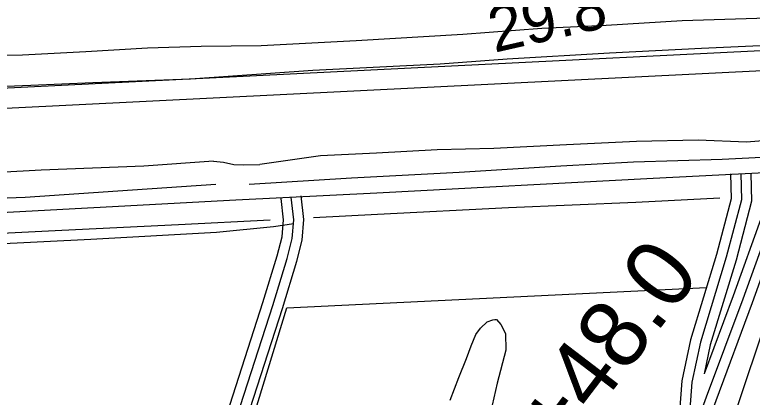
# Model space of a CAD drawing. Extents: x 3297772 to 3335630, y 634068 to 659439.
# Drawn here: x 3330240 to 3331326, y 644667 to 645230 of the extents above; entities that cross this region are included whole.
import ezdxf

# ---------------------------------------------------------------- set-up
doc = ezdxf.new("R2010")
doc.units = 0
for name, color, linetype in [('V-DTCH-CNTR', 7, 'Continuous'), ('V-FLOD-BASE', 7, 'Continuous'), ('V-LEVE-TOET', 7, 'Continuous'), ('V-RIVR-RANG', 7, 'Continuous'), ('V-ROAD-CNTR', 7, 'Continuous'), ('V-SITE-VEGE', 7, 'Continuous'), ('V-SURV-IDEN', 7, 'Continuous'), ('V-SURV-LINE', 7, 'Continuous'), ('V-TOPO-SHOR', 7, 'Continuous'), ('V-UTIL-LINE', 7, 'Continuous')]:
    doc.layers.add(name, color=color, linetype=linetype)

msp = doc.modelspace()

# ---------------------------------------------------------------- linework, layer by layer
at = {"layer": 'V-DTCH-CNTR'}
for points in [[(3330650.4, 644922.4), (3330620.8, 644918.1), (3330536.8, 644909.3), (3330351.7, 644899), (3330202.7, 644891.8), (3330031.6, 644885), (3329912.9, 644877), (3329903.6, 644873.9), (3329893.9, 644865.3), (3329882.2, 644838.1), (3329870.4, 644792.2), (3329872, 644779.8), (3329883.6, 644767.7), (3329927.2, 644745.5), (3329995.6, 644720.9), (3330134.4, 644676.8), (3330282.9, 644628.4), (3330438.4, 644573.4), (3330452.8, 644562.5), (3330477.3, 644539.9), (3330530.5, 644517.2)], [(3331338.7, 644758.7), (3331279.3, 644581.4), (3331213.4, 644360.6), (3331154.8, 644170), (3331138, 644102.8), (3331140.3, 644093.4), (3331157.4, 644076.3), (3331163.2, 644065), (3331154.6, 644025.8), (3331099.2, 643854.3)]]:
    msp.add_lwpolyline(points, dxfattribs=at)
at = {"layer": 'V-FLOD-BASE'}
msp.add_lwpolyline([(3329075.4, 645065.6), (3329181.4, 645069.7), (3329301, 645075.7), (3329468.5, 645084.8), (3329631.1, 645097.4), (3329730.9, 645103.5), (3329836.9, 645110.3), (3329923.2, 645113.3), (3329989.4, 645114), (3330118.2, 645120.5), (3330263.3, 645126.1), (3330354.7, 645130.2), (3330498.2, 645135.5), (3330678.5, 645148.4), (3330866.2, 645157.5), (3330964.5, 645165.1), (3331115.4, 645173.9), (3331250.8, 645180.7), (3331391.3, 645187.1), (3331544.1, 645193.1), (3331585.9, 645197.7), (3331629.3, 645203.4), (3331672.6, 645213.8)], dxfattribs=at)
at = {"layer": 'V-LEVE-TOET'}
for points in [[(3329320.5, 645126.1), (3329430.8, 645131.5), (3329551.3, 645142.3), (3329662.3, 645148.4), (3329784.7, 645155.7), (3329921.2, 645163), (3330045.2, 645164.4), (3330144.9, 645170.5), (3330251.2, 645170.8), (3330344.3, 645175.8), (3330435, 645181.1), (3330514, 645183.4), (3330602.4, 645184.8), (3330742.4, 645192.1), (3330899.6, 645201.3), (3331015.7, 645210.2), (3331110.7, 645214.4), (3331222.6, 645221.3), (3331348.1, 645225.4)], [(3331383.3, 645048), (3331317.2, 645042.2), (3331246.1, 645045.4), (3331155.3, 645043.5), (3331052.1, 645038.6), (3330945, 645033.2), (3330861.7, 645031), (3330772.5, 645026), (3330689.6, 645022.2), (3330600.4, 645009.8)], [(3330532.4, 645014.5), (3330429.6, 645007.2), (3330278.6, 645001.1), (3330153.1, 644994.6), (3330013.5, 644989.3), (3329885.2, 644981.7), (3329760.5, 644971.6), (3329635, 644964.7), (3329489.1, 644959), (3329362, 644946.3), (3329245.5, 644938.2), (3329112.9, 644932.1), (3328981.1, 644925.6), (3328912.7, 644919.8), (3328837.6, 644910.5), (3328670.2, 644897.4)], [(3330532.4, 645014.5), (3330546.8, 645012.9), (3330562.2, 645009.6), (3330575.8, 645009.1), (3330600.4, 645009.8)]]:
    msp.add_lwpolyline(points, dxfattribs=at)
at = {"layer": 'V-ROAD-CNTR'}
for points in [[(3325736.1, 644715.3), (3326147.1, 644722), (3326579.4, 644746.2), (3326860.4, 644766.7), (3327040, 644782.7), (3327405, 644790.9), (3327728.6, 644805), (3328365, 644841.2), (3328961, 644870), (3329423.1, 644898), (3329955.7, 644924.8), (3330565.3, 644957.4), (3330772.6, 644967.9), (3331179.9, 644989.5), (3331441, 645002.9)], [(3331363.5, 645004.4), (3331340, 644934.8), (3331297.5, 644816.5), (3331254.7, 644701.9)], [(3331377.7, 644999.7), (3331354.2, 644929.8), (3331311.5, 644811.3), (3331257.8, 644667.3), (3331227.6, 644585.4), (3331200.8, 644505.1), (3331116.1, 644248.6), (3330933.1, 643667.9), (3330742.9, 643076.2), (3330534.9, 642422.4)], [(3331391.9, 644994.9), (3331368.3, 644924.9), (3331325.6, 644806.2), (3331271.9, 644662), (3331241.7, 644580.4), (3331215.1, 644500.4), (3331130.3, 644244), (3330947.4, 643663.4), (3330757.2, 643071.6), (3330549.2, 642417.8)], [(3331293.7, 644995.8), (3331294.4, 644959.3), (3331273, 644877.2), (3331234.6, 644751.9), (3331221.9, 644691.5), (3331214.6, 644593.9)], [(3331308.7, 644996.1), (3331309.5, 644957.6), (3331287.4, 644873.1), (3331249.2, 644748.2), (3331236.7, 644689.4), (3331229.4, 644590.2)], [(3331323.7, 644996.4), (3331324.5, 644955.8), (3331301.8, 644869), (3331263.7, 644744.4), (3331254.7, 644701.9)], [(3330284.2, 643841.6), (3330326.4, 643963.9), (3330442.8, 644304.7), (3330552.3, 644643.1), (3330605.1, 644806.5), (3330626, 644875.4), (3330633.2, 644903.3), (3330635.4, 644928.2), (3330631.7, 644959.7)], [(3330288.8, 643808.9), (3330340.5, 643959), (3330457, 644300), (3330566.6, 644638.5), (3330619.4, 644802), (3330640.5, 644871.4), (3330648, 644900.8), (3330650.5, 644928.4), (3330646.6, 644961.5)], [(3330298.5, 643792.1), (3330354.7, 643954.1), (3330471.3, 644295.2), (3330580.9, 644633.9), (3330633.7, 644797.6), (3330654.9, 644867.4), (3330662.8, 644898.2), (3330665.5, 644928.6), (3330661.5, 644963.3)]]:
    msp.add_lwpolyline(points, dxfattribs=at)
at = {"layer": 'V-SITE-VEGE'}
msp.add_lwpolyline([(3330880.9, 644662.9), (3330893.7, 644696.3), (3330905, 644724.3), (3330911.7, 644743), (3330918.7, 644759.7), (3330925.3, 644769), (3330935, 644778), (3330943.6, 644781.1), (3330946.7, 644781.5), (3330949.1, 644781.5), (3330955.3, 644774.4), (3330962.3, 644761.2), (3330962.6, 644736.7), (3330950.1, 644687.7), (3330935.3, 644623.2)], dxfattribs=at)
at = {"layer": 'V-SURV-LINE'}
for points in [[(3329001, 645061.3), (3331556, 645188.1)], [(3331557.5, 645158.2), (3329002.4, 645031.3)]]:
    msp.add_lwpolyline(points, dxfattribs=at)
at = {"layer": 'V-TOPO-SHOR'}
for points in [[(3331369.1, 645021.4), (3331281.2, 645016.8), (3331150.9, 645013.1), (3331043.5, 645007.3), (3330894.2, 644997.8)], [(3330894.2, 644997.8), (3330735.5, 644989.4), (3330585, 644979.9)], [(3330535.6, 644980.3), (3330413, 644971.9), (3330254.7, 644961.2), (3330054.8, 644953.7), (3329889.4, 644941.8)], [(3331277.6, 644960), (3331153.9, 644953.9), (3330966.4, 644945.6), (3330773.9, 644936.1), (3330679.4, 644931.2)], [(3330615.6, 644927.7), (3330480.7, 644920.9), (3330308.7, 644912.5), (3330161, 644904.9), (3329987.1, 644895.4), (3329888.8, 644886.8)]]:
    msp.add_lwpolyline(points, dxfattribs=at)
at = {"layer": 'V-UTIL-LINE'}
for points in [[(3330640.2, 644798.6), (3331258.2, 644828.5)], [(3330502.7, 644350.2), (3330640.2, 644798.6)]]:
    msp.add_lwpolyline(points, dxfattribs=at)

# ---------------------------------------------------------------- texts
at = {"layer": 'V-RIVR-RANG'}
msp.add_text('29.8', height=67, rotation=12.7883, dxfattribs=at).set_placement((3330945.8, 645173.8))
at = {"layer": 'V-SURV-IDEN'}
msp.add_text('4712+48.0', height=100, rotation=52.6562, dxfattribs=at).set_placement((3330865.4, 644342.7))

doc.saveas('drawing.dxf')
